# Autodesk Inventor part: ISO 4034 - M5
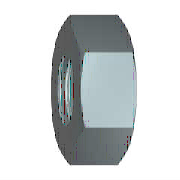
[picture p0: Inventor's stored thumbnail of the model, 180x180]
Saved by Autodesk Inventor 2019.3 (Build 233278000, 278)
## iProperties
Created: 2018-01
Part Number: ISO 4034 - M5
Material: Ocel
Description: Šestihranné matice. Výrobní řada C
Document SubType Name: Modeling
Standard: ISO 4034
Designer: B-hon
Standards Organization: CSN
Language: cs-CZ
Size Designation: M5
Categories: <MemberInstance><Categories><Category DisplayName="Spojovací materiál" InternalName="e4da775c-781d-43d5-af7c-5136215cf5a6" Mnemonic="FSTN"><Category DisplayName
Density: 7.85 g/cm^3
Appearance: Plech
IsCustomPart: 0
Author: B-hon
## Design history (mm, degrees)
sketch "Náčrt1"
  geometry: L1 (-4.619, 0)-(-2.309, 4); L2 (-2.309, 4)-(2.309, 4); L3 (2.309, 4)-(4.619, 0); L4 (4.619, 0)-(2.309, -4); L5 (2.309, -4)-(-2.309, -4); L6 (-2.309, -4)-(-4.619, 0); 2 further points
  constraints: 12 end point, 1 coincident, 1 horizontal, 11 other
  dimensions: "d0" = 9.2376 distance of L3.end L1.start (= 1.1547 x SW)
extrude "Těleso" new body sketch "Náčrt1" distance "d1" = 5.6 (= KOH); taper "d2" = 0 deg
sketch "Náčrt2"
  geometry: L1 (0, 2.309)-(0, 4.619) reference; L2 (0, 4.619)-(5.6, 4.619) reference; L3 (5.6, 2.309)-(5.6, 4.619) reference; L4 (-1.12, 0)-(6.72, 0) reference; L5 (0.357, 4.619)-(0, 4); L6 (5.243, 4.619)-(5.6, 4)
  constraints: 4 end point, 4 point on line
  dimensions: "d3" = 30 deg angle of L1 L5 (= ANG1); "d4" = 30 deg angle of L3 L6 (= ANG2); "d5" = 8 diameter of L5.end L4 (= SW0); "d6" = 8 diameter of L6.end L4 (= SW01)
revolve "Zkosení1" sketch "Náčrt2" stored, may be unused: angle "d7" = 90 deg
sketch "Náčrt3"
  geometry: A1 r 4 centre (0, 0) between (-2, -3.464) and (2, -3.464) reference; 1 further point
  constraints: 1 coincident
hole "Závit" sketch "Náčrt3" at (0, 0) diameter "d25" = 4.134; stored, may be unused: countersink angle "d29" = 82 deg, drill point angle "d31" = 118 deg; dims "d26" = 6, "d27" = 4, "d28" = 2, "d30" = 8
workaxis "Work Axis1"
workplane "Work Plane1"
body "Solid1"
chamfer "Zkosení2" distance "d8" = 0.43301 (= -0.5 x GD1 + 0.5 x NND); stored, may be unused: angle "d9" = 30 deg, second distance "d40" = 0.43301 (= -0.5 x GD1 + 0.5 x NND)
chamfer "Zkosení3" distance "d10" = 0.43301 (= -0.5 x GD1 + 0.5 x NND); stored, may be unused: angle "d11" = 30 deg, second distance "d41" = 0.43301 (= -0.5 x GD1 + 0.5 x NND)
other parameters: "ANG1" = 30 deg [user parameter; used in 1 equation term], "ANG2" = 30 deg [user parameter; used in 1 equation term], "NND" = 5 [user parameter; used in 4 equation terms], "KOH" = 5.6 [user parameter; used in 1 equation term], "SW" = 8 [user parameter; used in 4 equation terms], "SW0" = 8 (= SW) [user parameter; used in 1 equation term], "SW01" = 8 (= SW) [user parameter; used in 1 equation term], "GD1" = 4.13397 (computed from THREADDIA, PTC, TOA) [user parameter; used in 4 equation terms], "d13" = 0, "d14" = 0, "d39" = 0, "d42" = 0, "GUL" = 0.43301 (= 0.541266 x PTC) [user parameter], "TPU" = 12.5 (computed from PTC) [user parameter], "THREADDIA" = 5 [user parameter; used in 1 equation term], "TOA" = 30 deg [user parameter; used in 1 equation term], "PTC" = 0.8 [user parameter; used in 4 equation terms], "E0" = 9.24 (= 1.155 x SW) [user parameter], "GAL" = 0.43301 (= 0.541266 x PTC) [user parameter]
